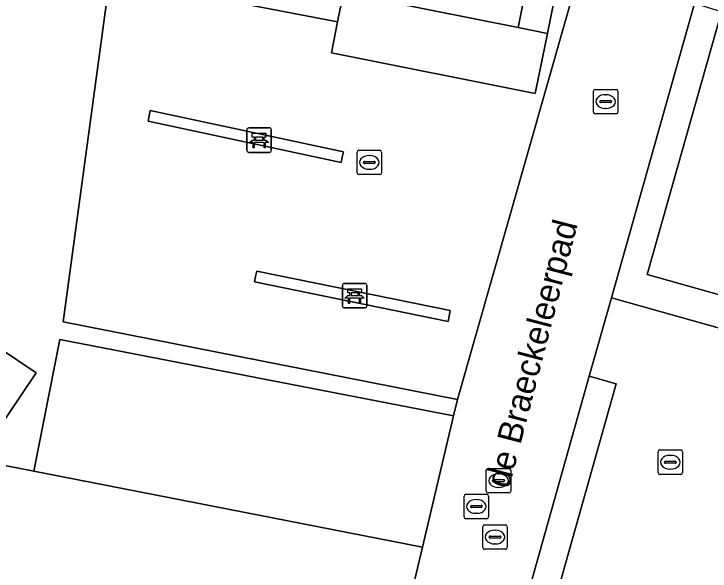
# Model space of a CAD drawing. Extents: x 162803 to 163818, y 381639 to 382475.
# Drawn here: x 163041.17 to 163069.63, y 382112.42 to 382135.2 of the extents above; entities that cross this region are included whole.
import ezdxf

# ---------------------------------------------------------------- set-up
doc = ezdxf.new("R2010")
doc.units = 0
for name, color, linetype in [('IMGEO_Bank', 7, 'Continuous'), ('IMGEO_Erf', 7, 'Continuous'), ('IMGEO_Groenvoorziening', 7, 'Continuous'), ('IMGEO_Kolk', 7, 'Continuous'), ('IMGEO_Openbare_ruimte_label', 7, 'Continuous'), ('IMGEO_Parkeervlak_open', 7, 'Continuous'), ('IMGEO_Rijbaan_lokaal_gesloten', 7, 'Continuous'), ('IMGEO_Rijbaan_lokaal_open', 7, 'Continuous'), ('IMGEO_Rioolput', 7, 'Continuous'), ('IMGEO_Terreindeel_gesloten', 7, 'Continuous'), ('IMGEO_Voetpad_op_trap', 7, 'Continuous'), ('IMGEO_Voetpad_open', 7, 'Continuous')]:
    doc.layers.add(name, color=color, linetype=linetype)

msp = doc.modelspace()

# ---------------------------------------------------------------- linework, layer by layer
at = {"layer": 'IMGEO_Bank'}
for p, q in [((163050.768, 382130.543), (163051.609, 382130.543)), ((163051.609, 382130.543), (163050.768, 382130.543)), ((163050.693, 382129.618), (163050.693, 382130.459)), ((163050.693, 382130.459), (163050.693, 382129.618)), ((163051.693, 382130.468), (163051.693, 382129.627)), ((163051.693, 382129.627), (163051.693, 382130.468)), ((163051.39, 382129.941), (163050.997, 382129.941)), ((163051.002, 382130.049), (163051.002, 382130.155)), ((163051.046, 382130.155), (163051.046, 382130.049)), ((163051.334, 382130.161), (163051.052, 382130.161)), ((163051.052, 382130.043), (163051.334, 382130.043)), ((163051.34, 382130.049), (163051.34, 382130.155)), ((163051.384, 382130.155), (163051.384, 382130.049)), ((163051.618, 382129.543), (163050.777, 382129.543)), ((163050.777, 382129.543), (163051.618, 382129.543)), ((163054.597, 382123.258), (163054.597, 382124.099)), ((163054.597, 382124.099), (163054.597, 382123.258)), ((163054.672, 382124.183), (163055.513, 382124.183)), ((163055.513, 382124.183), (163054.672, 382124.183)), ((163055.597, 382124.108), (163055.597, 382123.267)), ((163055.597, 382123.267), (163055.597, 382124.108)), ((163054.906, 382123.689), (163054.906, 382123.795)), ((163054.95, 382123.795), (163054.95, 382123.689)), ((163055.238, 382123.801), (163054.956, 382123.801)), ((163054.956, 382123.683), (163055.238, 382123.683)), ((163055.244, 382123.689), (163055.244, 382123.795)), ((163055.288, 382123.795), (163055.288, 382123.689)), ((163055.294, 382123.581), (163054.901, 382123.581)), ((163055.522, 382123.183), (163054.681, 382123.183)), ((163054.681, 382123.183), (163055.522, 382123.183))]:
    msp.add_line(p, q, dxfattribs=at)
for points in [[(163050.996, 382130.161), (163050.91, 382130.161), (163050.91, 382130.322), (163051.473, 382130.322), (163051.473, 382130.161), (163051.39, 382130.161)], [(163050.94, 382129.941), (163050.798, 382129.941), (163050.91, 382130.043), (163050.996, 382130.043)], [(163050.99, 382129.934), (163050.99, 382129.727), (163050.947, 382129.727), (163050.947, 382129.934)], [(163051.39, 382130.043), (163051.473, 382130.043), (163051.585, 382129.941), (163051.446, 382129.941)], [(163051.44, 382129.934), (163051.44, 382129.727), (163051.396, 382129.727), (163051.396, 382129.934)], [(163054.9, 382123.801), (163054.814, 382123.801), (163054.814, 382123.962), (163055.377, 382123.962), (163055.377, 382123.801), (163055.294, 382123.801)], [(163054.844, 382123.581), (163054.702, 382123.581), (163054.814, 382123.683), (163054.9, 382123.683)], [(163055.294, 382123.683), (163055.377, 382123.683), (163055.489, 382123.581), (163055.35, 382123.581)], [(163054.894, 382123.574), (163054.894, 382123.367), (163054.851, 382123.367), (163054.851, 382123.574)], [(163055.344, 382123.574), (163055.344, 382123.367), (163055.3, 382123.367), (163055.3, 382123.574)]]:
    msp.add_lwpolyline(points, dxfattribs=at)
for centre, radius, start, end in [((163050.771, 382130.465), 0.0779, 92.4484, 184.2845), ((163050.771, 382130.465), 0.0779, 92.4484, 184.2845), ((163051.615, 382130.465), 0.0779, 2.4484, 94.2845), ((163051.615, 382130.465), 0.0779, 2.4484, 94.2845), ((163050.94, 382129.934), 0.00671, 2.8957, 87.1043), ((163050.997, 382129.934), 0.00671, 92.8957, 177.1043), ((163050.995, 382130.154), 0.00671, 2.8957, 87.1043), ((163050.995, 382130.05), 0.00671, 272.8957, 357.1043), ((163051.052, 382130.154), 0.00671, 92.8957, 177.1043), ((163051.052, 382130.05), 0.00671, 182.8957, 267.1043), ((163051.334, 382130.154), 0.00671, 2.8957, 87.1043), ((163051.334, 382130.05), 0.00671, 272.8957, 357.1043), ((163051.391, 382130.154), 0.00671, 92.8957, 177.1043), ((163051.391, 382130.05), 0.00671, 182.8957, 267.1043), ((163051.389, 382129.934), 0.00671, 2.8957, 87.1043), ((163051.446, 382129.934), 0.00671, 92.8957, 177.1043), ((163050.771, 382129.621), 0.0779, 182.4484, 274.2845), ((163050.771, 382129.621), 0.0779, 182.4484, 274.2845), ((163051.615, 382129.621), 0.0779, 272.4484, 4.2845), ((163051.615, 382129.621), 0.0779, 272.4484, 4.2845), ((163054.675, 382124.105), 0.0779, 92.4484, 184.2845), ((163054.675, 382124.105), 0.0779, 92.4484, 184.2845), ((163055.519, 382124.105), 0.0779, 2.4484, 94.2845), ((163055.519, 382124.105), 0.0779, 2.4484, 94.2845), ((163054.899, 382123.794), 0.00671, 2.8957, 87.1043), ((163054.899, 382123.69), 0.00671, 272.8957, 357.1043), ((163054.956, 382123.794), 0.00671, 92.8957, 177.1043), ((163054.956, 382123.69), 0.00671, 182.8957, 267.1043), ((163055.238, 382123.794), 0.00671, 2.8957, 87.1043), ((163055.238, 382123.69), 0.00671, 272.8957, 357.1043), ((163055.295, 382123.794), 0.00671, 92.8957, 177.1043), ((163055.295, 382123.69), 0.00671, 182.8957, 267.1043), ((163054.844, 382123.574), 0.00671, 2.8957, 87.1043), ((163054.901, 382123.574), 0.00671, 92.8957, 177.1043), ((163055.293, 382123.574), 0.00671, 2.8957, 87.1043), ((163055.35, 382123.574), 0.00671, 92.8957, 177.1043), ((163054.675, 382123.261), 0.0779, 182.4484, 274.2845), ((163054.675, 382123.261), 0.0779, 182.4484, 274.2845), ((163055.519, 382123.261), 0.0779, 272.4484, 4.2845), ((163055.519, 382123.261), 0.0779, 272.4484, 4.2845)]:
    msp.add_arc(centre, radius, start, end, dxfattribs=at)
at = {"layer": 'IMGEO_Erf'}
msp.add_lwpolyline([(163045.126, 382136.995), (163038.119, 382138.416), (163038.036, 382138.113), (163032.552, 382139.225), (163032.499, 382139.236), (163032.613, 382139.529), (163021.351, 382141.798), (163018.766, 382130.712), (163019.585, 382130.131), (163026.747, 382125.047), (163029.53, 382128.968), (163042.075, 382120.52), (163039.675, 382116.955), (163041.983, 382116.5), (163043.045, 382121.889), (163059.142, 382118.76), (163059.303, 382119.439), (163043.189, 382122.617)], close=True, dxfattribs=at)
at = {"layer": 'IMGEO_Groenvoorziening'}
for points in [[(163062.976, 382134.408), (163061.788, 382134.646), (163054.637, 382136.079), (163054.404, 382134.885), (163054.156, 382133.614), (163062.479, 382131.943)], [(163068.983, 382135.625), (163065.602, 382123.594), (163082.771, 382118.765), (163083.126, 382120.021), (163067.058, 382124.545), (163070.095, 382135.286)], [(163064.68, 382120.384), (163058.467, 382098.276), (163059.564, 382097.963), (163065.785, 382120.07)]]:
    msp.add_lwpolyline(points, close=True, dxfattribs=at)
at = {"layer": 'IMGEO_Kolk'}
for p, q in [((163064.857, 382131.193), (163064.857, 382132.045)), ((163064.932, 382132.119), (163065.784, 382132.119)), ((163065.858, 382132.045), (163065.858, 382131.193)), ((163065.116, 382131.613), (163065.116, 382131.625)), ((163065.159, 382131.662), (163065.557, 382131.662)), ((163065.345, 382131.899), (163065.37, 382131.899)), ((163065.6, 382131.625), (163065.6, 382131.613)), ((163065.554, 382131.576), (163065.156, 382131.576)), ((163065.368, 382131.339), (163065.343, 382131.339)), ((163065.784, 382131.119), (163064.932, 382131.119)), ((163055.275, 382129.631), (163056.127, 382129.631)), ((163055.2, 382128.705), (163055.2, 382129.557)), ((163055.688, 382129.411), (163055.713, 382129.411)), ((163056.201, 382129.557), (163056.201, 382128.705)), ((163055.459, 382129.125), (163055.459, 382129.137)), ((163055.897, 382129.088), (163055.499, 382129.088)), ((163055.502, 382129.174), (163055.9, 382129.174)), ((163055.943, 382129.137), (163055.943, 382129.125)), ((163055.711, 382128.851), (163055.686, 382128.851)), ((163056.127, 382128.631), (163055.275, 382128.631)), ((163067.501, 382116.444), (163067.501, 382117.296)), ((163067.576, 382117.37), (163068.428, 382117.37)), ((163067.989, 382117.15), (163068.014, 382117.15)), ((163068.502, 382117.296), (163068.502, 382116.444)), ((163067.76, 382116.864), (163067.76, 382116.876)), ((163068.198, 382116.827), (163067.8, 382116.827)), ((163067.803, 382116.913), (163068.201, 382116.913)), ((163068.244, 382116.876), (163068.244, 382116.864)), ((163060.555, 382116.613), (163061.407, 382116.613)), ((163068.012, 382116.59), (163067.987, 382116.59)), ((163060.48, 382115.687), (163060.48, 382116.539)), ((163060.968, 382116.393), (163060.993, 382116.393)), ((163061.481, 382116.539), (163061.481, 382115.687)), ((163068.428, 382116.37), (163067.576, 382116.37)), ((163060.739, 382116.107), (163060.739, 382116.119)), ((163061.177, 382116.07), (163060.779, 382116.07)), ((163060.782, 382116.156), (163061.18, 382116.156)), ((163061.223, 382116.119), (163061.223, 382116.107)), ((163060.991, 382115.833), (163060.966, 382115.833)), ((163061.407, 382115.613), (163060.555, 382115.613))]:
    msp.add_line(p, q, dxfattribs=at)
for points in [[(163064.857, 382131.193), (163064.857, 382132.045)], [(163064.932, 382132.119), (163065.784, 382132.119)], [(163065.858, 382132.045), (163065.858, 382131.193)], [(163065.784, 382131.119), (163064.932, 382131.119)], [(163055.275, 382129.631), (163056.127, 382129.631)], [(163055.2, 382128.705), (163055.2, 382129.557)], [(163056.201, 382129.557), (163056.201, 382128.705)], [(163056.127, 382128.631), (163055.275, 382128.631)], [(163067.501, 382116.444), (163067.501, 382117.296)], [(163067.576, 382117.37), (163068.428, 382117.37)], [(163068.502, 382117.296), (163068.502, 382116.444)], [(163060.555, 382116.613), (163061.407, 382116.613)], [(163060.48, 382115.687), (163060.48, 382116.539)], [(163061.481, 382116.539), (163061.481, 382115.687)], [(163068.428, 382116.37), (163067.576, 382116.37)], [(163061.407, 382115.613), (163060.555, 382115.613)]]:
    msp.add_lwpolyline(points, dxfattribs=at)
for centre, radius, start, end in [((163064.934, 382132.043), 0.0765, 91.552, 178.448), ((163064.934, 382132.043), 0.0765, 91.552, 178.448), ((163065.782, 382132.043), 0.0765, 1.552, 88.448), ((163065.782, 382132.043), 0.0765, 1.552, 88.448), ((163065.156, 382131.622), 0.0403, 85.8775, 175.7526), ((163065.561, 382131.624), 0.0386, 1.7309, 96.639), ((163065.153, 382131.612), 0.0366, 178.938, 274.7102), ((163065.557, 382131.619), 0.043, 264.8664, 352.4533), ((163064.934, 382131.195), 0.0765, 181.552, 268.448), ((163064.934, 382131.195), 0.0765, 181.552, 268.448), ((163065.782, 382131.195), 0.0765, 271.552, 358.448), ((163065.782, 382131.195), 0.0765, 271.552, 358.448), ((163055.277, 382129.555), 0.0765, 91.552, 178.448), ((163055.277, 382129.555), 0.0765, 91.552, 178.448), ((163056.125, 382129.555), 0.0765, 1.552, 88.448), ((163056.125, 382129.555), 0.0765, 1.552, 88.448), ((163055.499, 382129.134), 0.0403, 85.8775, 175.7526), ((163055.496, 382129.124), 0.0366, 178.938, 274.7102), ((163055.9, 382129.131), 0.043, 264.8664, 352.4533), ((163055.904, 382129.136), 0.0386, 1.7309, 96.639), ((163055.277, 382128.707), 0.0765, 181.552, 268.448), ((163055.277, 382128.707), 0.0765, 181.552, 268.448), ((163056.125, 382128.707), 0.0765, 271.552, 358.448), ((163056.125, 382128.707), 0.0765, 271.552, 358.448), ((163067.578, 382117.294), 0.0765, 91.552, 178.448), ((163067.578, 382117.294), 0.0765, 91.552, 178.448), ((163068.426, 382117.294), 0.0765, 1.552, 88.448), ((163068.426, 382117.294), 0.0765, 1.552, 88.448), ((163067.8, 382116.873), 0.0403, 85.8775, 175.7526), ((163067.797, 382116.863), 0.0366, 178.938, 274.7102), ((163068.201, 382116.87), 0.043, 264.8664, 352.4533), ((163068.205, 382116.875), 0.0386, 1.7309, 96.639), ((163060.557, 382116.537), 0.0765, 91.552, 178.448), ((163060.557, 382116.537), 0.0765, 91.552, 178.448), ((163061.405, 382116.537), 0.0765, 1.552, 88.448), ((163061.405, 382116.537), 0.0765, 1.552, 88.448), ((163067.578, 382116.446), 0.0765, 181.552, 268.448), ((163067.578, 382116.446), 0.0765, 181.552, 268.448), ((163068.426, 382116.446), 0.0765, 271.552, 358.448), ((163068.426, 382116.446), 0.0765, 271.552, 358.448), ((163060.779, 382116.116), 0.0403, 85.8775, 175.7526), ((163060.776, 382116.106), 0.0366, 178.938, 274.7102), ((163061.18, 382116.113), 0.043, 264.8664, 352.4533), ((163061.184, 382116.118), 0.0386, 1.7309, 96.639), ((163060.557, 382115.689), 0.0765, 181.552, 268.448), ((163060.557, 382115.689), 0.0765, 181.552, 268.448), ((163061.405, 382115.689), 0.0765, 271.552, 358.448), ((163061.405, 382115.689), 0.0765, 271.552, 358.448)]:
    msp.add_arc(centre, radius, start, end, dxfattribs=at)
for centre, major_axis, ratio, start_param, end_param in [((163065.344, 382131.619), (-0.387, 0.002), 0.722429, 4.712389, 7.853982), ((163065.369, 382131.619), (-0.39, 0.002), 0.717154, 1.570796, 4.712389), ((163055.687, 382129.131), (-0.387, 0.002), 0.722429, 4.712389, 7.853982), ((163055.712, 382129.131), (-0.39, 0.002), 0.717154, 1.570796, 4.712389), ((163067.988, 382116.87), (-0.387, 0.002), 0.722429, 4.712389, 7.853982), ((163068.013, 382116.87), (-0.39, 0.002), 0.717154, 1.570796, 4.712389), ((163060.967, 382116.113), (-0.387, 0.002), 0.722429, 4.712389, 7.853982), ((163060.992, 382116.113), (-0.39, 0.002), 0.717154, 1.570796, 4.712389)]:
    msp.add_ellipse(centre, major_axis=major_axis, ratio=ratio, start_param=start_param, end_param=end_param, dxfattribs=at)
at = {"layer": 'IMGEO_Parkeervlak_open'}
msp.add_lwpolyline([(163070.095, 382135.286), (163067.058, 382124.545), (163083.126, 382120.021), (163082.771, 382118.765), (163065.602, 382123.594), (163064.68, 382120.384), (163065.785, 382120.07), (163059.564, 382097.963), (163058.467, 382098.276), (163057.526, 382094.992), (163060.376, 382094.128), (163059.693, 382091.916), (163065.424, 382090.228), (163065.988, 382092.126), (163080.019, 382087.859), (163079.424, 382085.941), (163081.605, 382085.282), (163089.146, 382112.062), (163090.13, 382111.765), (163090.529, 382113.186), (163091.858, 382117.918), (163090.853, 382118.199), (163098.192, 382144.406)], dxfattribs=at)
msp.add_lwpolyline([(163059.142, 382118.76), (163043.045, 382121.889), (163041.983, 382116.5), (163057.869, 382113.398)], close=True, dxfattribs=at)
at = {"layer": 'IMGEO_Rijbaan_lokaal_gesloten'}
msp.add_lwpolyline([(163057.869, 382113.398), (163041.983, 382116.5), (163039.675, 382116.955), (163042.075, 382120.52), (163029.53, 382128.968), (163026.747, 382125.047), (163019.585, 382130.131), (163018.766, 382130.712), (163021.351, 382141.798), (163015.071, 382143.064), (163007.934, 382131.42), (163007.397, 382130.544), (163012.846, 382127.275), (163013.016, 382127.522), (163012.945, 382127.595), (163013.116, 382127.842), (163046.085, 382105.143), (163047.735, 382107.541), (163055.804, 382104.695)], close=True, dxfattribs=at)
at = {"layer": 'IMGEO_Rijbaan_lokaal_open'}
msp.add_lwpolyline([(163065.602, 382123.594), (163068.983, 382135.625), (163069.93, 382139.013), (163073.693, 382152.429), (163069.465, 382155.136), (163059.303, 382119.439), (163059.142, 382118.76), (163057.869, 382113.398), (163055.804, 382104.695), (163051.707, 382093.075), (163056.494, 382091.577), (163057.526, 382094.992), (163058.467, 382098.276), (163064.68, 382120.384)], close=True, dxfattribs=at)
at = {"layer": 'IMGEO_Rioolput'}
for p, q in [((163059.571, 382114.633), (163059.571, 382115.485)), ((163059.646, 382115.559), (163060.498, 382115.559)), ((163060.572, 382115.485), (163060.572, 382114.633)), ((163060.059, 382115.339), (163060.084, 382115.339)), ((163059.83, 382115.053), (163059.83, 382115.065)), ((163060.268, 382115.016), (163059.87, 382115.016)), ((163059.873, 382115.102), (163060.271, 382115.102)), ((163060.314, 382115.065), (163060.314, 382115.053)), ((163060.498, 382114.559), (163059.646, 382114.559)), ((163060.082, 382114.779), (163060.057, 382114.779)), ((163060.41, 382114.307), (163061.262, 382114.307)), ((163060.335, 382113.381), (163060.335, 382114.233)), ((163060.823, 382114.087), (163060.848, 382114.087)), ((163061.336, 382114.233), (163061.336, 382113.381)), ((163060.594, 382113.801), (163060.594, 382113.813)), ((163061.032, 382113.764), (163060.634, 382113.764)), ((163060.637, 382113.85), (163061.035, 382113.85)), ((163061.078, 382113.813), (163061.078, 382113.801)), ((163060.846, 382113.527), (163060.821, 382113.527)), ((163061.262, 382113.307), (163060.41, 382113.307))]:
    msp.add_line(p, q, dxfattribs=at)
for points in [[(163059.571, 382114.633), (163059.571, 382115.485)], [(163059.646, 382115.559), (163060.498, 382115.559)], [(163060.572, 382115.485), (163060.572, 382114.633)], [(163060.498, 382114.559), (163059.646, 382114.559)], [(163060.41, 382114.307), (163061.262, 382114.307)], [(163060.335, 382113.381), (163060.335, 382114.233)], [(163061.336, 382114.233), (163061.336, 382113.381)], [(163061.262, 382113.307), (163060.41, 382113.307)]]:
    msp.add_lwpolyline(points, dxfattribs=at)
for centre, radius, start, end in [((163059.648, 382115.483), 0.0765, 91.552, 178.448), ((163059.648, 382115.483), 0.0765, 91.552, 178.448), ((163060.496, 382115.483), 0.0765, 1.552, 88.448), ((163060.496, 382115.483), 0.0765, 1.552, 88.448), ((163059.87, 382115.062), 0.0403, 85.8775, 175.7526), ((163059.867, 382115.052), 0.0366, 178.938, 274.7102), ((163060.271, 382115.059), 0.043, 264.8664, 352.4533), ((163060.275, 382115.064), 0.0386, 1.7309, 96.639), ((163059.648, 382114.635), 0.0765, 181.552, 268.448), ((163059.648, 382114.635), 0.0765, 181.552, 268.448), ((163060.496, 382114.635), 0.0765, 271.552, 358.448), ((163060.496, 382114.635), 0.0765, 271.552, 358.448), ((163060.412, 382114.231), 0.0765, 91.552, 178.448), ((163060.412, 382114.231), 0.0765, 91.552, 178.448), ((163061.26, 382114.231), 0.0765, 1.552, 88.448), ((163061.26, 382114.231), 0.0765, 1.552, 88.448), ((163060.634, 382113.81), 0.0403, 85.8775, 175.7526), ((163060.631, 382113.8), 0.0366, 178.938, 274.7102), ((163061.035, 382113.807), 0.043, 264.8664, 352.4533), ((163061.039, 382113.812), 0.0386, 1.7309, 96.639), ((163060.412, 382113.383), 0.0765, 181.552, 268.448), ((163060.412, 382113.383), 0.0765, 181.552, 268.448), ((163061.26, 382113.383), 0.0765, 271.552, 358.448), ((163061.26, 382113.383), 0.0765, 271.552, 358.448)]:
    msp.add_arc(centre, radius, start, end, dxfattribs=at)
for centre, major_axis, ratio, start_param, end_param in [((163060.058, 382115.059), (-0.387, 0.002), 0.722429, 4.712389, 7.853982), ((163060.083, 382115.059), (-0.39, 0.002), 0.717154, 1.570796, 4.712389), ((163060.822, 382113.807), (-0.387, 0.002), 0.722429, 4.712389, 7.853982), ((163060.847, 382113.807), (-0.39, 0.002), 0.717154, 1.570796, 4.712389)]:
    msp.add_ellipse(centre, major_axis=major_axis, ratio=ratio, start_param=start_param, end_param=end_param, dxfattribs=at)
at = {"layer": 'IMGEO_Terreindeel_gesloten'}
for points in [[(163046.747, 382131.26), (163046.7, 382131.04), (163046.653, 382130.82), (163054.542, 382129.128), (163054.589, 382129.348), (163054.636, 382129.568)], [(163051.096, 382124.682), (163051.051, 382124.462), (163051.006, 382124.242), (163058.916, 382122.629), (163058.961, 382122.849), (163059.006, 382123.069)]]:
    msp.add_lwpolyline(points, close=True, dxfattribs=at)
at = {"layer": 'IMGEO_Voetpad_op_trap'}
for points in [[(163053.722, 382151.695), (163053.975, 382152.875), (163051.227, 382153.411), (163047.914, 382136.14), (163054.404, 382134.885), (163054.637, 382136.079), (163049.313, 382137.13), (163052.19, 382151.984)], [(163063.812, 382150.905), (163063.56, 382149.721), (163064.736, 382149.487), (163061.788, 382134.646), (163062.976, 382134.408), (163066.178, 382150.431)]]:
    msp.add_lwpolyline(points, close=True, dxfattribs=at)
at = {"layer": 'IMGEO_Voetpad_open'}
msp.add_lwpolyline([(163045.126, 382136.995), (163043.189, 382122.617), (163059.303, 382119.439), (163069.465, 382155.136)], dxfattribs=at)
for points in [[(163054.156, 382133.614), (163054.404, 382134.885), (163047.914, 382136.14), (163051.227, 382153.411), (163053.975, 382152.875), (163063.812, 382150.905), (163066.178, 382150.431), (163062.976, 382134.408), (163062.479, 382131.943)], [(163063.56, 382149.721), (163063.286, 382148.436), (163053.453, 382150.442), (163053.722, 382151.695), (163052.19, 382151.984), (163049.313, 382137.13), (163054.637, 382136.079), (163061.788, 382134.646), (163064.736, 382149.487)], [(163054.589, 382129.348), (163054.542, 382129.128), (163046.653, 382130.82), (163046.7, 382131.04), (163046.747, 382131.26), (163054.636, 382129.568)], [(163059.006, 382123.069), (163058.961, 382122.849), (163058.916, 382122.629), (163051.006, 382124.242), (163051.051, 382124.462), (163051.096, 382124.682)]]:
    msp.add_lwpolyline(points, close=True, dxfattribs=at)

# ---------------------------------------------------------------- texts
at = {"layer": 'IMGEO_Openbare_ruimte_label'}
msp.add_text('de Braeckeleerpad', height=1, rotation=75.4635, dxfattribs=at).set_placement((163061.406, 382115.756))

doc.saveas('drawing.dxf')
